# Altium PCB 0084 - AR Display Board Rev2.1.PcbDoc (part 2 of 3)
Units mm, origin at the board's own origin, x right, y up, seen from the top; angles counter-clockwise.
Board outline 127.7 x 27.2 mm, 4 copper layers (L1-TOP, L2-GND, L3-GND, L4-BOT), stack 1.571 mm thick; 141 components, 141 nets, 671 pads, 447 vias.
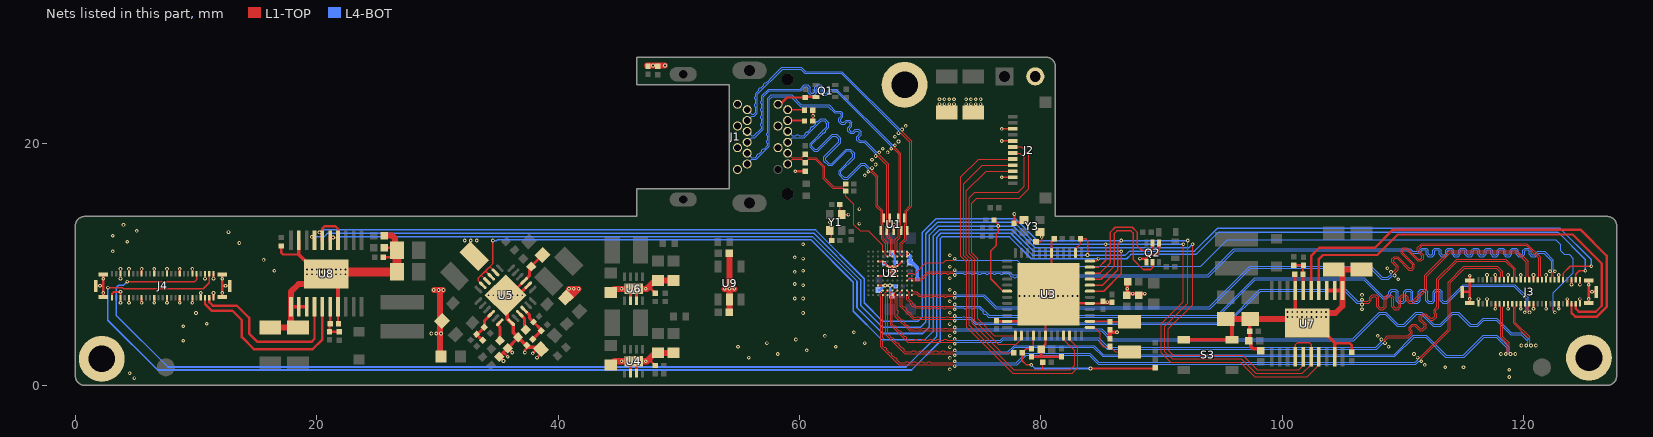
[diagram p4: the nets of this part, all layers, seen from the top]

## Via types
v1: diameter 0.3, hole 0.15, L1-TOP to L4-BOT, tented both sides, 445 vias
v2: diameter 0.25, hole 0.1, L1-TOP to L4-BOT, tented both sides, 2 vias

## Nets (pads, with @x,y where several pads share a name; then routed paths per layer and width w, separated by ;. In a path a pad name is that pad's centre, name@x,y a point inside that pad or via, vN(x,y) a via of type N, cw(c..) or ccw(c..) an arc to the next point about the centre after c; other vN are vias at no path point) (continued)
CN: C41.1 U5.18 | length 2
  L1-TOP w0.1: U5.18@34.944,4.999 U5.18@35.167,5.221
  L1-TOP w0.25: U5.18@35.167,5.221 35,5.055 35,5 35.182,4.818 C41.1@35.182,3.718
CP: C40.1 U5.21 | length 1.6
  L1-TOP w0.25: U5.21@36.829,5.929 37.2,5.557 37.2,4.547 C40.1@37.262,4.485
DP_AUX_CH_N: C3.2 J1.18 R2.2 U2.A4 | length 13.5
  L1-TOP w0.076: J1.18@59.015,18.34 59.389,18.714 60.186,18.714 R2.2@60.46,18.44 60.734,18.714 61.286,18.714 61.948,18.052 61.948,17.137 62.761,16.324 63.606,16.324 C3.2@63.83,16.1 63.83,15.67 64.5,15 64.5,13.326 65.026,12.8 65.7,12.8 66.9,11.6 U2.A4@66.9,11.075
DP_AUX_CH_P: C2.2 J1.16 R1.1 | length 6.8
  L1-TOP w0.076: J1.16@59.015,19.24 59.389,18.866 60.186,18.866 R1.1@60.46,19.14 60.734,18.866 61.349,18.866 62.1,18.116 62.1,17.2 62.824,16.476 63.606,16.476 C2.2@63.83,16.7
DP_CFG1: J1.4 R4.2 | length 1.4
  L1-TOP w0.15: J1.4@59.015,22.84 60.37,22.84 R4.2@60.41,22.8
DP_CFG2: J1.6 R3.2 | length 1.4
  L1-TOP w0.15: J1.6@59.015,21.94 60.37,21.94 R3.2@60.41,21.9
DP_HPD: J1.2 Q1.3 R23.2 | length 3.5
  L1-TOP w0.2: J1.2@58.215,23.09 58.975,23.85 R23.2@60.46,23.85 60.51,23.9 Q1.3@61.36,23.9
DP_LANE0_N: J1.10 U1.9 U2.A5 | length 28.7
  L1-TOP w0.076: v1(66,18) 66,17.808 66.5,17.308 66.5,14.876 66.905,14.471 66.905,13.395 66.945,13.355 66.945,12.171 67.3,11.816 U2.A5@67.3,11.075
  L4-BOT w0.076: J1.10@59.015,21.04 59.389,20.666 59.675,20.666 cw(c59.827,20.551) 59.98,20.666 60.2,20.666 60.341,20.666 60.45,20.775 cw(c60.639,20.802) 60.666,20.991 60.881,21.206 cw(c61.07,21.233) 61.097,21.422 61.312,21.637 cw(c61.501,21.664) 61.528,21.853 61.562,21.888 61.75,22.075 62.1,22.075 62.425,21.75 62.425,21.375 62.175,21.125 cw(c61.986,21.098) 61.959,20.909 61.875,20.825 61.025,19.975 61.025,19.8 61.275,19.55 61.459,19.55 62.709,20.8 63.066,20.8 63.402,20.463 63.402,20.102 62.175,18.875 62.175,18.65 62.448,18.377 62.662,18.377 63.862,19.577 64.213,19.577 64.577,19.213 64.577,18.877 63.425,17.725 63.425,17.5 63.7,17.225 63.934,17.225 65.112,18.402 65.405,18.402 65.808,18 v1(66,18)
DP_LANE0_P: J1.12 U1.1 U2.B5 | length 28.7
  L1-TOP w0.076: v1(65.7,17.7) 65.892,17.7 66.348,17.245 66.348,14.812 66.753,14.407 66.753,13.332 66.793,13.292 66.793,12.107 67.148,11.752 67.148,11.223 67.1,11.175 67.1,10.875 U2.B5@67.3,10.675
  L4-BOT w0.076: J1.12@59.015,20.14 59.389,20.514 60.404,20.514 61.813,21.923 62.037,21.923 62.273,21.687 62.273,21.438 60.873,20.038 60.873,19.737 61.212,19.398 61.523,19.398 62.773,20.648 63.002,20.648 63.25,20.4 63.25,20.166 62.023,18.938 62.023,18.587 62.384,18.225 62.725,18.225 63.925,19.425 64.15,19.425 64.425,19.15 64.425,18.941 63.273,17.788 63.273,17.437 63.637,17.073 63.998,17.073 65.175,18.25 65.342,18.25 65.7,17.892 v1(65.7,17.7)
DP_LANE1_N: J1.15 U1.8 U2.A6 | length 28.7
  L1-TOP w0.076: v1(66.6,19.3) 66.6,19.108 67.397,18.31 67.397,13.388 67.435,13.351 67.435,12.34 67.7,12.075 U2.A6@67.7,11.075
  L4-BOT w0.076: J1.15@55.665,19.24 56.039,18.866 56.351,18.866 56.458,18.974 56.458,19.082 56.566,19.189 56.674,19.189 56.889,19.405 56.889,19.513 56.997,19.621 57.105,19.621 57.321,19.836 57.36,19.876 57.36,20.028 57.284,20.104 57.284,20.257 57.36,20.333 57.36,20.638 57.284,20.714 57.284,20.866 57.36,20.942 57.36,21 57.36,23.776 57.659,24.075 59.341,24.075 60.163,23.252 62.455,23.252 62.98,22.728 63.394,22.728 63.59,22.532 63.59,22.243 63.402,22.055 63.402,21.892 63.508,21.785 63.671,21.785 63.859,21.974 64.149,21.974 64.344,21.778 64.344,21.489 64.156,21.3 64.156,21.137 64.262,21.031 64.425,21.031 64.614,21.219 64.903,21.219 65.099,21.024 65.099,20.734 64.91,20.546 64.91,20.383 65.017,20.277 65.431,20.277 65.707,20 66.408,19.3 v1(66.6,19.3)
DP_LANE1_P: J1.17 U1.2 U2.B6 | length 28.7
  L1-TOP w0.076: v1(66.3,19) 66.492,19 67.245,18.247 67.245,13.325 67.282,13.288 67.282,12.277 67.548,12.012 67.548,11.223 67.5,11.175 67.5,10.875 U2.B6@67.7,10.675
  L4-BOT w0.076: J1.17@55.665,18.34 56.039,18.714 56.414,18.714 57.512,19.812 57.512,23.712 57.723,23.923 59.277,23.923 60.1,23.1 62.392,23.1 62.917,22.575 63.331,22.575 63.438,22.469 63.438,22.306 63.249,22.118 63.249,21.828 63.445,21.633 63.734,21.633 63.922,21.821 64.086,21.821 64.192,21.715 64.192,21.552 64.004,21.363 64.004,21.074 64.199,20.879 64.489,20.879 64.677,21.067 64.84,21.067 64.946,20.961 64.946,20.797 64.758,20.609 64.758,20.32 64.953,20.124 65.368,20.124 65.555,19.937 66.3,19.192 v1(66.3,19)
DP_LANE2_N: J1.9 U1.4 U2.A7 | length 28.7
  L1-TOP w0.076: v1(67.9,19.9) 67.9,19.708 68.397,19.21 68.397,13.347 68.347,13.297 68.347,12.272 68.1,12.025 U2.A7@68.1,11.075
  L4-BOT w0.076: J1.9@55.665,21.04 56.039,20.666 56.226,20.666 56.86,21.301 56.86,21.453 56.784,21.529 56.784,21.682 56.86,21.758 56.86,22.063 56.784,22.139 56.784,22.291 56.86,22.367 56.86,22.672 56.784,22.748 56.784,22.901 56.86,22.977 56.86,23.282 56.784,23.358 56.784,23.51 56.86,23.587 56.86,23.775 56.86,23.976 57.434,24.55 59.85,24.55 60.053,24.55 60.395,24.893 60.672,24.893 60.876,24.688 60.876,24.323 60.992,24.207 61.142,24.207 61.257,24.323 61.257,24.688 61.462,24.893 61.738,24.893 61.943,24.688 61.943,24.323 62.058,24.207 62.209,24.207 62.551,24.55 63.058,24.55 67.708,19.9 v1(67.9,19.9)
DP_LANE2_P: J1.11 U1.7 U2.B7 | length 28.7
  L1-TOP w0.076: v1(67.6,19.6) 67.792,19.6 68.245,19.147 68.245,13.411 68.195,13.361 68.195,12.336 67.948,12.088 67.948,11.223 67.9,11.175 67.9,10.875 U2.B7@68.1,10.675
  L4-BOT w0.076: J1.11@55.665,20.14 56.039,20.514 56.289,20.514 57.012,21.237 57.012,23.912 57.498,24.398 59.918,24.398 60.116,24.398 60.458,24.74 60.609,24.74 60.724,24.625 60.724,24.26 60.929,24.055 61.205,24.055 61.41,24.26 61.41,24.625 61.525,24.74 61.675,24.74 61.791,24.625 61.791,24.26 61.995,24.055 62.272,24.055 62.614,24.398 62.995,24.398 67.6,19.792 v1(67.6,19.6)
DP_LANE3_N: J1.3 U1.5 U2.A8 | length 28.7
  L1-TOP w0.076: U2.A8@68.5,11.075 68.5,11.725 68.855,12.08 68.855,13.289 68.895,13.329 68.895,14.42 69.3,14.824 69.3,20.208 68.5,21.008 v1(68.5,21.2)
  L4-BOT w0.076: J1.3@55.665,22.84 56.039,22.466 56.2,22.466 56.36,22.626 56.36,22.9 56.36,23.052 56.284,23.129 56.284,23.281 56.36,23.357 56.36,23.662 56.284,23.738 56.284,23.891 56.36,23.967 56.36,24.1 56.36,24.176 56.5,24.316 56.615,24.43 56.615,24.538 56.722,24.646 56.83,24.646 57.046,24.861 57.046,24.969 57.153,25.077 57.261,25.077 57.477,25.292 57.584,25.4 58.537,26.352 60.148,26.352 60.5,26 63.508,26 68.308,21.2 v1(68.5,21.2)
DP_LANE3_P: J1.5 U1.6 U2.B8 | length 28.7
  L1-TOP w0.076: v1(68.2,20.9) 68.392,20.9 69.148,20.145 69.148,14.888 68.743,14.483 68.743,13.393 68.703,13.353 68.703,12.143 68.348,11.788 68.348,11.223 68.3,11.175 68.3,10.875 U2.B8@68.5,10.675
  L4-BOT w0.076: J1.5@55.665,21.94 56.039,22.314 56.263,22.314 56.512,22.563 56.512,24.112 58.6,26.2 60.084,26.2 60.437,25.848 63.445,25.848 68.2,21.092 v1(68.2,20.9)
FBL: C49.2 R35.2 R37.2 U7.16 | length 2.9
  L1-TOP w0.2: R35.2@100.96,9.95 C49.2@101.74,9.95 ; U7.16@101.75,7.844 U7.16@101.729,7.865 101.729,9.181 R37.2@101.71,9.2 101.71,9.92 C49.2@101.74,9.95 ; C49.2@101.76,9.97 C49.2@101.74,9.95
FBN: C36.2 R29.2 R30.2 U5.16 | length 3
  L1-TOP w0.25: R30.2@33.747,3.747 33.719,3.747 C36.2@33.233,4.233 33.316,4.233 R29.2@33.897,4.814 33.897,5.365 U5.16@34.46,5.929
FBP: C34.2 R26.2 R28.2 U5.22 | length 3.3
  L1-TOP w0.1: R26.2@38.597,4.519 R26.2@38.597,4.613
  L1-TOP w0.25: U5.22@37.182,6.282 37.644,5.82 37.644,5.566 C34.2@37.956,5.253 R26.2@38.597,4.613 ; R28.2@37.892,3.814 R26.2@38.597,4.519
FBR: C50.2 R36.2 R38.2 U8.16 | length 3
  L1-TOP w0.2: C50.2@20.96,4.43 20.96,4.45 C50.2@21.06,4.45 ; R38.2@21.01,5.1 21.118,5.208 U8.16@21.118,6.516 ; R38.2@21.06,5.1 C50.2@21.06,4.45 ; R36.2@21.86,4.45 C50.2@21.06,4.45
GND: C1.1 C4.1 C5.2 C6.2 C7.2 C8.2 C9.2 C10.1 C11.1 C12.1 C13.1 C14.1 C15.1 C16.1 C17.1 C18.1 C19.1 C20.1 C21.1 C22.1 C23.1 C24.1 C25.1 C26.2 C27.2 C28.1 C29.1 C30.1 C31.1 C32.1 C33.1 C35.2 C37.1 C38.1 C39.1 C40.2 C41.2 C42.1 C43.1 C44.1 C45.1 C46.1 C47.1 C48.1 C51.1 C52.1 C53.1 C54.1 C55.2 C56.2 C57.1 C58.2 C59.2 C60.1 C61.1 C62.1 CON2.2 J1.1 J1.7 J1.8 J1.13 J1.14 J1.19 J2.2 J2.8 J2.10 J3.1 J3.5 J3.6 J3.9 J3.10 J3.15 J3.16 J3.21 J3.22 J3.27 J3.28 J3.33 J3.34 J3.39 J3.40 J3.43 J3.46 J3.49 J3.50 J3.M J4.1 J4.5 J4.6 J4.9 J4.10 J4.15 J4.16 J4.21 J4.22 J4.27 J4.28 J4.33 J4.34 J4.39 J4.40 J4.43 J4.46 J4.49 J4.50 J4.M L4.2 pad.0 Q2.1 Q2.4 R2.1 R3.1 R4.1 R5.1 R27.1 R28.1 R34.1 R37.1 R38.1 R39.1 R40.1 R41.1 R42.1 S3.1 U1.3 U2.A9 U2.B9 U2.C3 U2.C4 U2.C8 U2.D5 U2.D6 U2.D7 U2.E5 U2.E6 U2.E7 U2.F3 U2.F4 U2.F5 U2.F6 U2.F7 U2.H3 U2.H4 U2.H5 U2.H6 U3.5 U3.18 U3.35 U3.42 U3.49 U4.2 U4.3 U4.9 U5.2 U5.3 U5.19 U5.25 U6.2 U6.3 U6.9 U7.9 U7.11 U7.12 U7.13 U7.17 U7.21 U8.9 U8.11 U8.12 U8.13 U8.17 U8.21 U9.2 Y1.2 Y1.4 Y3.2 Y3.4 | length 216.9
  L1-TOP w0.1: U5.25@35.775,7.467 U5.25@35.998,7.467 ; C40.2@36.626,3.848 36.815,3.848 C40.2@36.867,3.848 ; C33.1@38.71,10.796 C33.1@38.71,10.801 ; U4.9@46.01,1.75 v1(46.26,2) U4.9@46.51,1.75 ; U6.9@46.01,7.75 v1(46.26,8) U6.9@46.51,7.75 ; C43.1@48.01,8.35 C43.1@48.36,8.7 ; C32.1@48.11,2.35 48.46,2.7 C32.1@48.31,2.85 ; U3.49@78.375,5.3 80.375,7.3 U3.49@80.625,7.55 ; U3.49@80.875,7.8 U3.49@80.625,7.55 ; U3.49@81.375,6.8 U3.49@80.625,7.55 ; U7.21@101.23,5.979 101.709,5.5 U7.21@102.05,5.159 102.641,5.159 U7.21@102.741,5.159 ; U7.21@101.9,6 U7.21@103.25,4.65 ; U7.21@102.379,5.488 U7.21@102.841,5.95
  L1-TOP w0.125: v1(76.75,17.25) J2.2@77.66,17.25 77.635,17.25 J2.2@77.66,17.275 ; v1(76.75,20.25) J2.8@77.66,20.25 ; v1(76.75,21.25) J2.10@77.66,21.25
  L1-TOP w0.127: R3.1@61.11,21.9 R4.1@61.11,22.8 R4.1@61.135,22.775 ; Y1.2@62.46,12.85 62.63,12.68 C7.2@62.63,12 ; Y1.2@62.5,12.85 v1(62.5,13.5) ; Y1.4@63.29,14.32 Y1.4@63.46,14.15 ; C8.2@63.33,15 63.33,14.32 Y1.4@63.5,14.15 v1(64.05,14.15)
  L1-TOP w0.15: v1(77.8,14.2) 77.8,13.47 C59.2@77.76,13.43 77.83,13.5 78.41,13.5 Y3.4@78.61,13.7 ; C58.2@79.59,11.9 79.96,11.9 80.06,12 80.06,12.55 Y3.2@79.91,12.7
  L1-TOP w0.152: J4.1@3.05,7.25 3.05,7.6 3.2,7.75 v1(3.75,7.75) ; U2.H3@66.5,8.275 U2.H4@66.9,8.275 U2.H5@67.3,8.275 U2.H6@67.7,8.275 ; U2.F3@66.5,9.075 66.502,9.073 67.298,9.073 U2.F5@67.3,9.075 U2.F6@67.7,9.075 ; U2.C3@66.5,10.275 66.502,10.273 66.902,10.273 U2.D5@67.3,9.875 67.302,9.873 U2.D6@67.7,9.873 ; U2.E5@67.3,9.475 U2.E6@67.7,9.475 ; U2.F7@68.1,9.075 U2.F6@67.7,9.075 ; U2.E7@68.1,9.475 U2.E6@67.7,9.475 ; U2.C8@68.5,10.275 U2.D7@68.1,9.875 68.098,9.873 U2.D6@67.7,9.873 ; C13.1@76.3,5.355 C13.1@76.355,5.3 ; U2.F6@67.7,9.075 U2.E6@67.7,9.475 ; U2.E6@67.7,9.475 U2.D6@67.7,9.873 ; U2.B9@68.9,10.675 69,10.775 v1(69,10.875) 69,10.975 U2.A9@68.9,11.075 U2.B9@68.9,10.675
  L1-TOP w0.175: U3.5@84.05,6.8 C17.1@85.8,6.8
  L1-TOP w0.18: v1(3.75,6.85) J4.5@3.75,7.25 v1(3.75,7.75) ; v1(3.75,8.85) J4.6@3.75,9.25 v1(3.75,9.65) ; v1(4.45,6.85) J4.9@4.45,7.25 ; J4.10@4.45,9.25 v1(4.45,9.65) ; v1(5.5,6.85) J4.15@5.5,7.25 ; J4.16@5.5,9.25 v1(5.5,9.65) ; v1(6.55,6.85) J4.21@6.55,7.25 ; J4.22@6.55,9.25 v1(6.55,9.65) ; v1(7.6,6.85) J4.27@7.6,7.25 ; J4.28@7.6,9.25 v1(7.6,9.65) ; v1(8.65,6.85) J4.33@8.65,7.25 ; J4.34@8.65,9.25 v1(8.65,9.65) ; v1(9.7,6.85) J4.39@9.7,7.25 ; J4.40@9.7,9.25 v1(9.7,9.65) ; J4.43@10.4,7.25 v1(10.4,7.65) ; v1(10.75,8.85) J4.46@10.75,9.25 ; J4.49@11.45,7.25 v1(11.45,7.65) ; v1(11.45,8.85) J4.50@11.45,9.25 ; J3.M@115.385,6.815 J3.M@115.525,6.815 ; J3.M@115.385,8.685 J3.M@115.525,8.685 v1(115.525,9.085) ; J3.1@116.25,6.75 v1(116.25,7.15) ; J3.5@116.95,6.75 v1(116.95,7.15) ; J3.6@116.95,8.75 v1(116.95,9.15) ; v1(117.65,6.35) J3.9@117.65,6.75 ; J3.10@117.65,8.75 v1(117.65,9.15) ; v1(118.7,6.35) J3.15@118.7,6.75 ; J3.16@118.7,8.75 v1(118.7,9.15) ; v1(119.75,6.35) J3.21@119.75,6.75 ; J3.22@119.75,8.75 v1(119.75,9.15) ; v1(120.8,6.35) J3.27@120.8,6.75 ; J3.28@120.8,8.75 v1(120.8,9.15) ; v1(121.85,6.35) J3.33@121.85,6.75 ; J3.34@121.85,8.75 v1(121.85,9.15) ; v1(122.9,6.35) J3.39@122.9,6.75 ; J3.40@122.9,8.75 v1(122.9,9.15) ; J3.43@123.6,6.75 v1(123.6,7.15) ; v1(123.95,8.35) J3.46@123.95,8.75 ; J3.49@124.65,6.75 v1(124.65,7.15) ; v1(124.65,8.35) J3.50@124.65,8.75
  L1-TOP w0.2: J4.M@1.7,8.25 2.325,8.25 ; J4.M@2.325,7.315 v1(2.325,7.665) 2.325,8.25 ; J4.M@2.325,9.185 v1(2.325,8.835) 2.325,8.25 ; J4.M@12.175,7.315 12.175,8.25 ; J4.M@12.175,9.185 v1(12.175,8.835) 12.175,8.25 ; J4.M@12.8,8.25 12.175,8.25 ; R42.1@17.06,11.55 17.06,11 17.218,10.842 18.518,10.842 ; R38.1@21.71,5.1 21.768,5.158 U8.17@21.768,6.516 ; R41.1@25.51,10.6 C47.1@26.66,10.6 ; C56.2@25.61,11.4 26.66,11.4 C47.1@26.66,11.2 ; C35.2@35.118,2.382 v1(35.475,2.025) ; 35.456,2.719 35.481,2.719 v1(35.825,2.375) ; C41.2@35.818,3.082 36.175,2.725 v1(36.2,2.725) ; v1(37.25,2.725) 37.25,2.925 R28.1@37.5,3.175 ; v1(37.9,2.65) 38.225,2.975 C30.1@38.225,3.175 ; v1(38.25,2.3) 38.578,2.628 C30.1@38.578,3.001 ; v1@47.36,2 47.71,2 R27.1@48.06,1.65 ; v1@47.36,8 47.71,8 R34.1@48.06,7.65 ; v1(59.64,17.74) R2.1@60.46,17.74 ; U1.3@67.82,12.83 v1(67.82,13.34) ; C13.1@76.355,5.3 U3.49@78.375,5.3 ; C4.1@79.2,2.37 80,2.37 ; C9.2@80.01,3 80.01,2.38 80,2.37 ; C9.2@80.16,2.85 80.16,3.2 80.375,3.415 U3.49@80.375,7.3 ; U3.49@80.875,7.8 80.875,11.93 C12.1@81.095,12.15 ; U3.49@81.375,6.8 U3.5@84.05,6.8 ; C11.1@81.7,2.37 80,2.37 ; v1(88.2,10.5) 88.76,10.5 ; Q2.4@88.76,10.2 88.76,10.5 ; 89.76,11.4 89.76,11 89.56,10.8 88.9,10.8 88.76,10.66 88.76,10.5 ; R37.1@101.01,9.2 101.079,9.131 U7.17@101.079,7.865 ; U7.21@102.05,5.159 102.609,4.6 U7.21@103.2,4.6 ; 104.329,3.531 104.36,3.5 105.56,3.5 105.76,3.3 R40.1@105.76,2.75 ; J3.M@114.9,7.75 115.525,7.75 ; J3.M@115.525,6.815 v1(115.525,7.165) 115.525,7.75 ; J3.M@115.525,8.685 115.525,7.75 ; J3.M@125.375,6.815 v1(125.375,7.165) 125.375,7.75 ; J3.M@125.375,8.685 v1(125.375,8.335) 125.375,7.75 ; J3.M@126,7.75 125.375,7.75
  L1-TOP w0.25: C35.2@35.118,2.382 35.456,2.719 C41.2@35.818,3.082 36.682,3.945 C40.2@36.682,3.982 C40.2@36.815,3.848 ; U5.19@36.121,5.221 U5.19@36.325,5.018 ; R28.1@37.345,3.319 R28.1@37.397,3.319 ; U5.2@37.536,8.297 36.705,7.467 35.998,7.467 U5.3@37.182,8.651 37.644,9.113 37.644,9.73 C37.1@37.762,9.848 C33.1@38.71,10.796 ; U4.2@46.01,1.005 U4.9@46.01,1.75 ; U6.2@46.01,7.005 U6.9@46.01,7.75 ; U4.3@46.51,1.005 U4.9@46.51,1.75 ; U6.3@46.51,7.005 U6.9@46.51,7.75
  L1-TOP w0.3: U8.11@17.868,6.516 U8.12@18.518,6.516 U8.13@19.168,6.516 ; U8.9@18.518,12.016 18.518,10.842 19.625,9.735 U8.21@19.625,9.7 ; U8.21@19.925,8.35 U8.21@20.25,8.675 ; U8.21@20.468,8.893 U8.21@20.797,9.222 ; U8.21@21.322,8.697 U8.21@20.797,9.222 ; U8.21@21.372,8.647 U8.21@21.672,8.347 ; U8.17@21.768,6.516 U8.21@21.768,8.251 ; C38.1@30.326,5.332 C38.1@30.332,5.332 ; U5.25@35.775,7.467 35.775,5.525 36.3,5 36.3,4.364 C40.2@36.682,3.982 ; C40.2@36.815,3.848 R28.1@37.345,3.319 ; R28.1@37.397,3.319 R28.1@37.541,3.175 ; R28.1@37.5,3.175 C30.1@38.225,3.175 ; C15.1@85.135,6.87 C17.1@85.9,6.87 ; C26.2@85.725,3.88 C27.2@85.725,4.62 ; C27.2@85.8,4.4 v1(86.3,4.4) ; C16.1@87.1,7.45 C16.1@87.15,7.5 ; C10.1@87.21,8.6 87.15,8.6 C16.1@87.15,7.5 ; C14.1@88.1,7.4 C14.1@88.3,7.6 ; v1(88.6,7.6) C14.1@88.3,7.6 ; 89.76,11.4 Q2.1@89.76,11.8 ; S3.1@91.825,3.775 S3.1@95.825,3.775 95.825,4.975 C45.1@95.3,5.5 C45.1@94.925,5.125 ; C46.1@97.35,5.5 97.31,5.46 R39.1@97.31,4.5 97.31,3.8 C55.2@97.21,3.7 97.375,3.535 97.375,3.225 97.575,3.025 98.025,3.025 C57.1@98.2,2.85 ; U7.21@101.079,6.13 U7.17@101.079,7.865 ; U7.21@102.05,5.159 U7.21@102.379,5.488 ; U7.21@102.49,4.84 U7.21@102.96,4.84 ; U7.21@102.641,5.159 U7.21@102.96,4.84 ; U7.21@103.2,4.6 U7.21@102.96,4.84 ; U7.13@103.679,7.865 U7.12@104.329,7.865 U7.11@104.979,7.865 ; U7.9@104.329,2.365 104.329,3.531 103.02,4.84 U7.21@102.96,4.84 ; U8.21@19.625,9.7 20.103,9.222 U8.21@20.797,9.222 ; U8.21@19.625,9.7 20.319,9.7 U8.21@20.797,9.222 ; C16.1@87.15,7.5 87.25,7.6 v1(87.6,7.6) C14.1@88.3,7.6
  L1-TOP w0.5: C54.1@16.16,4.8 C53.1@17.868,4.8 ; C53.1@18.46,4.8 C53.1@17.868,4.8 ; U8.21@19.975,8.85 19.525,8.4 18.5,8.4 17.868,7.768 U8.11@17.868,6.516 C53.1@17.868,4.8 ; U8.21@20.797,9.222 U8.21@20.975,9.4 ; C60.1@25.61,12.4 26.25,12.4 26.5,12.15 26.5,11.56 C47.1@26.66,11.4 ; v1(29.7,7.9) v1(30.1,7.9) v1@30.451,7.9 ; v1@30.2,7.9 30.2,5.511 C38.1@30.378,5.332 30.2,5.154 30.2,2.5 C39.1@30.3,2.4 ; L4.2@33.068,10.69 L4.2@33.26,10.882 ; C29.1@40.9,7.531 C29.1@40.9,7.7 ; C28.1@44.36,1.7 44.66,2 v1(46.26,2) 47.36,2 48.06,2.7 C32.1@48.16,2.7 ; C42.1@44.36,7.7 44.66,8 v1(45.76,8) v1(46.26,8) v1(46.76,8) 47.36,8 48.06,8.7 C43.1@48.26,8.7 48.36,8.7 C44.1@49.56,8.7 ; C1.1@47.36,26.5 v1(48.86,26.5) ; C32.1@48.31,2.85 C32.1@48.16,2.7 ; C31.1@49.56,2.7 48.46,2.7 C32.1@48.26,2.7 C32.1@48.16,2.7 ; v1(53.8,8) v1(54.2,8) ; C5.2@54.175,6.05 54.2,6.075 U9.2@54.2,7.1 v1(54.2,8) ; C6.2@54.175,10.95 54.2,10.925 v1(54.2,8) ; v1(54.6,8) v1(54.2,8) ; C45.1@95.3,5.5 C46.1@97.35,5.5 101.709,5.5 U7.21@101.909,5.5 ; U7.21@101.9,6 104.4,6 104.979,6.579 U7.11@104.979,7.865 104.979,9.581 104.96,9.6 C52.1@104.26,9.6 C51.1@106.56,9.6 ; C29.1@40.634,7.266 40.966,7.266 v1(41.7,8) v1(41.3,8) v1@41.2,8 ; C29.1@40.634,7.266 40.634,7.434 C29.1@40.8,7.6 ; C29.1@40.634,7.266 40.8,7.431 C29.1@40.8,7.6 ; C29.1@40.8,7.6 C29.1@40.9,7.7 ; C29.1@40.9,7.7 v1(40.9,8) v1@41.2,8 ; C29.1@40.9,7.7 v1@41.2,8
  L1-TOP w0.75: U8.21@20.975,9.4 C48.1@26.66,9.4 26.66,10.6 C47.1@26.66,11.2
  L4-BOT w0.2: C18.1@66.56,7.9 66.66,7.9 67.035,8.275 v1(67.1,8.275) v1(67.5,8.275) ; C19.1@67.01,10.12 67.09,10.12 67.475,9.735 v1(67.475,9.68) ; C24.1@67.66,7.45 67.5,7.61 v1(67.5,8.275) ; C22.1@67.66,10.95 67.66,10.84 67.898,10.602 v1(67.898,9.68) ; C25.1@67.98,8.2 67.905,8.275 v1(67.5,8.275)
  L4-BOT w0.3: v1(69,10.875) 69.16,10.715 C20.1@69.16,10.2 69.31,10.2 69.74,9.77 C21.1@69.74,8.8
  other v1: 4.9,0.6 118.8,0.7 4.5,1 118.8,1.3 72.46,1.325 113.5,1.5 115,1.5 111.8,1.7 45.26,2 45.76,2 46.76,2 47.26,2 72.46,2.275 55.8,2.3 58.2,2.6 110.9,2.6 118.1,2.6 119.3,2.6 60.6,2.9 72.46,3.175 54.9,3.2 63,3.2 108.8,3.2 119.8,3.3 121,3.3 57.3,3.5 65.4,3.5 8.95,3.7 59.7,3.8 62.1,4.1 107.9,4.1 72.46,4.125 29.5,4.3 29.9,4.3 30.3,4.3 64.5,4.4 8.95,4.9 72.46,5.075 10.9,5.1 100.425,5.675 100.825,5.675 101.225,5.675 101.625,5.675 102.025,5.675 102.425,5.675 102.825,5.675 103.225,5.675 103.625,5.675 10,6 60.3,6 72.46,6.025 100.425,6.075 100.825,6.075 101.225,6.075 101.625,6.075 102.025,6.075 102.425,6.075 102.825,6.075 103.225,6.075 103.625,6.075 106.6,6.3 85.5,6.9 72.46,6.975 59.6,7.2 60.3,7.2 78.225,7.4 78.625,7.4 79.025,7.4 79.425,7.4 79.825,7.4 80.225,7.4 80.625,7.4 81.025,7.4 81.425,7.4 81.825,7.4 82.225,7.4 82.625,7.4 83.025,7.4 34.225,7.475 34.625,7.475 35.025,7.475 35.425,7.475 35.825,7.475 36.225,7.475 36.625,7.475 37.025,7.475 106.6,7.5 12.175,7.665 125.65,7.75 30.5,7.9 72.46,7.925 45.26,8 47.26,8 87.15,8 2.05,8.25 12.45,8.25 60.3,8.3 59.6,8.4 109.6,8.8 72.46,8.875 19.2,9.2 19.6,9.2 20,9.2 20.4,9.2 20.8,9.2 21.2,9.2 21.6,9.2 22,9.2 22.4,9.2 67.475,9.275 67.898,9.275 59.6,9.4 16.5,9.5 60.3,9.5 19.2,9.6 19.6,9.6 20,9.6 20.4,9.6 20.8,9.6 21.2,9.6 21.6,9.6 22,9.6 22.4,9.6 108.7,9.7 72.46,9.825 15.6,10.4 60.3,10.5 59.6,10.6 72.46,10.775 3.1,11.1 60.3,11.7 13.6,11.8 4.3,11.9 32.26,12 32.76,12 33.26,12 80.06,12.3 3.1,12.4 12.7,12.7 5.1,12.8 4,13.3 64.96,13.4 64.96,14.6 65.4,17.4 66.3,18.3 66,18.7 67.3,19.3 66.9,19.6 68.2,20.2 67.9,20.6 68.8,21.5 61.125,22.325 71.6,23.3 72,23.3 72.4,23.3 72.8,23.3 73.8,23.3 74.2,23.3 74.6,23.3 75,23.3 71.6,23.7 72,23.7 72.4,23.7 72.8,23.7 73.8,23.7 74.2,23.7 74.6,23.7 75,23.7 47.86,26.5
LCD_BIAS_EN: U3.7 U5.8 U5.9 U5.10 U5.11 | length 77.5
  L1-TOP w0.127: U5.11@33.753,8.297 33.4,8.65 33.4,8.9 33.6,9.1 ; U5.10@34.106,8.651 33.657,9.1 33.6,9.1 ; 34.371,9.8 U5.8@34.813,9.358 ; U5.9@34.46,9.004 34,9.464 34,9.5 ; v1(34.6,12) 34.6,10.1 34,9.5 ; U3.7@84.05,7.8 85.2,7.8 86.66,9.26 v1(86.66,11.1) ; 33.6,9.1 34,9.5
  L4-BOT w0.127: v1(34.6,12) 34.9,12 34.975,12.075 60.925,12.075 64.46,8.54 64.46,6.14 66.8,3.8 70.4,3.8 71.06,4.46 71.06,12.36 71.6,12.9 77.6,12.9 79.4,11.1 v1(86.66,11.1)
LCD_BL_EN: U3.8 U7.4 U7.6 U8.4 U8.6 | length 121.7
  L1-TOP w0.1: v1(92.16,12) 92.16,6.8 90.26,4.9 90.26,2.8 90.86,2.2 96.6,2.2 97.8,1 101.66,1 102.379,1.719 U7.6@102.379,2.365
  L1-TOP w0.127: U3.8@84.05,8.3 85.1,8.3 86.37,9.57 86.37,11.71 v1(86.66,12) ; U7.4@101.079,2.365 101.079,3.379 101.25,3.55 102.25,3.55 102.379,3.421 U7.6@102.379,2.365
  L1-TOP w0.2: U8.6@20.468,12.016 20.468,12.989 20.661,13.182 21.561,13.182 21.768,12.975 U8.4@21.768,12.016
  L1-TOP w0.3: v1(20.235,12.675) 20.468,12.675 U8.6@20.468,12.016
  L4-BOT w0.127: v1(20.235,12.675) 20.435,12.875 61.325,12.875 65.36,8.84 65.36,6.84 66.9,5.3 69.8,5.3 70.16,5.66 70.16,12.66 71.3,13.8 77.9,13.8 79.7,12 v1(92.16,12)
LCD_BL_FAULT: R10.1 U3.30 U7.5 U8.5 | length 114.7
  L1-TOP w0.1: v1(92.56,11.7) 92.56,6.7 90.56,4.7 90.56,2.9 90.96,2.5 96.7,2.5 97.9,1.3 101.36,1.3 101.729,1.669 U7.5@101.729,2.365
  L1-TOP w0.127: R10.1@76.11,13.7 76.46,13.35 76.46,12.7 76.31,12.55 76.31,11.61 75.835,11.135 75.835,8.825 76.86,7.8 U3.30@77.2,7.8
  L1-TOP w0.3: U8.5@21.118,12.016 21.118,12.25 v1(21.36,12.25)
  L4-BOT w0.127: v1(21.36,12.25) 21.65,12.25 21.725,12.325 61.075,12.325 64.76,8.64 64.76,6.44 66.9,4.3 70.2,4.3 70.76,4.86 70.76,12.46 71.5,13.2 v1(76.46,13.2) 77.7,13.2 79.5,11.4 92.26,11.4 v1(92.56,11.7)
LCD_BL_K1_L: J3.47 U7.14 | length 34.2
  L1-TOP w0.2: U7.14@103.029,7.865 103.029,10.469 103.36,10.8 107.86,10.8 109.56,12.5 124.05,12.5 126.46,10.09 126.46,6.6 125.96,6.1 124.56,6.1 124.3,6.36 J3.47@124.3,6.75
LCD_BL_K1_R: J4.47 U8.14 | length 14
  L1-TOP w0.2: J4.47@11.1,7.25 11.1,6.9 11.4,6.6 13.4,6.6 14.4,5.6 14.4,4.3 15.1,3.6 19.56,3.6 19.818,3.858 U8.14@19.818,6.516
LCD_BL_K2_L: J3.45 U7.15 | length 37.5
  L1-TOP w0.2: U7.15@102.379,7.865 102.379,10.719 103.06,11.4 107.66,11.4 109.16,12.9 124.7,12.9 126.86,10.74 126.86,6.5 126.06,5.7 124.26,5.7 123.95,6.01 J3.45@123.95,6.75
LCD_BL_K2_R: J4.45 U8.15 | length 15.6
  L1-TOP w0.2: J4.45@10.75,7.25 10.75,6.75 11.3,6.2 13,6.2 13.8,5.4 13.8,4 14.8,3 19.66,3 20.468,3.808 U8.15@20.468,6.516
LCD_BL_LEDPWM: J3.48 J4.48 U3.12 | length 151.4
  L1-TOP w0.127: v1(2.7,8.1) 3.9,8.1 4,8 10.6,8 11.1,8.5 J4.48@11.1,9.25 ; U3.12@84.05,10.3 84.56,10.3 v1(84.76,10.5) ; J3.48@124.3,8.75 124.3,9.2 124.6,9.5 v1(125.1,9.5)
  L4-BOT w0.127: v1(2.7,8.1) 2.7,5.4 6.825,1.275 69.275,1.275 71.66,3.66 71.66,12.16 71.8,12.3 77.4,12.3 79.2,10.5 v1(84.76,10.5) 87.1,10.5 87.45,10.85 92.85,10.85 94.7,12.7 122.825,12.7 125.1,10.425 v1(125.1,9.5)
LCD_BL_PWM: U3.11 U7.7 U8.7 | length 113.3
  L1-TOP w0.1: v1(91.8,11.7) 91.8,6.94 89.96,5.1 89.96,2.7 90.76,1.9 96.5,1.9 97.7,0.7 102.06,0.7 103.029,1.669 U7.7@103.029,2.365
  L1-TOP w0.127: U3.11@84.05,9.8 84.8,9.8 85.36,10.36 v1(85.36,11.7)
  L1-TOP w0.3: v1(19.585,12.3) U8.7@19.8,12.3
  L4-BOT w0.127: v1(19.585,12.3) 20.6,12.3 20.9,12.6 61.2,12.6 65.06,8.74 65.06,6.64 66.9,4.8 70,4.8 70.46,5.26 70.46,12.56 71.4,13.5 77.8,13.5 79.6,11.7 v1(85.36,11.7) 85.37,11.69 v1@91.8,11.69
LCD_RESET_N: J3.42 J4.42 R12.1 U3.14 | length 152.7
  L1-TOP w0.127: v1(4.3,8.6) 9.9,8.6 10.05,8.75 J4.42@10.05,9.25 ; U3.14@82.875,10.975 82.875,11.315 83.275,11.715 R12.1@83.275,12.15 83.71,12.15 83.86,12 v1(83.86,10.8) ; J3.42@123.25,8.75 123.25,9.275 123.85,9.875 v1(125.6,9.875)
  L4-BOT w0.127: v1(4.3,8.6) 4,8.3 3.6,8.3 3.4,8.1 3.4,5.8 7.675,1.525 68.825,1.525 71.36,4.06 71.36,12.26 71.7,12.6 77.5,12.6 79.3,10.8 v1(83.86,10.8) 87,10.8 87.325,11.125 92.725,11.125 94.6,13 123,13 125.6,10.4 v1(125.6,9.875)
MCU_EXT2: J2.7 U3.37 | length 23.1
  L1-TOP w0.1: J2.7@77.66,19.75 78.35,19.75 79,19.1 79,16.3 78.2,15.5 74.7,15.5 74.275,15.075 74.275,10.985 74.75,10.51 74.75,5.51 76.135,4.125 U3.37@77.875,4.125
MCU_EXT3: J2.6 U3.38 | length 24
  L1-TOP w0.1: J2.6@77.66,19.25 78.25,19.25 78.6,18.9 78.6,16.5 78.1,16 74.5,16 74.05,15.55 74.05,10.91 74.525,10.435 74.525,5.335 76.46,3.4 77.96,3.4 78.375,3.815 U3.38@78.375,4.125
MCU_LED0: Q2.2 U3.10 | length 10.2
  L1-TOP w0.127: U3.10@84.05,9.3 84.9,9.3 85.76,10.16 85.76,12.7 86.16,13.1 87.56,13.1 87.96,12.7 87.96,11.6 88.36,11.2 89.1,11.2 89.26,11.36 Q2.2@89.26,11.8
MCU_LED1: Q2.5 U3.9 | length 11.6
  L1-TOP w0.127: U3.9@84.05,8.8 85,8.8 86.06,9.86 86.06,12.56 86.3,12.8 87.46,12.8 87.66,12.6 87.66,10.4 88.46,9.6 89.1,9.6 89.26,9.76 Q2.5@89.26,10.2
MCU_RESET_N: C4.2 R13.2 R15.2 U3.40 | length 14.1
  L1-TOP w0.127: v1(79.2,1.7) 78.8,1.7 78.45,2.05 R13.2@78.45,2.7 78.78,3.03 C4.2@79.2,3.03 ; C4.2@79.26,3.03 C4.2@79.2,3.03 ; U3.40@79.375,4.125 79.375,3.215 79.19,3.03 C4.2@79.2,3.03 ; v1(84.1,1.4) 89.36,1.4 R15.2@89.46,1.5
  L4-BOT w0.127: v1(79.2,1.7) 79.5,1.4 v1(84.1,1.4)
MCU_SWD_CLK: J2.4 R9.1 U3.45 | length 30.5
  L1-TOP w0.1: J2.4@77.66,18.25 75.15,18.25 73.6,16.7 73.6,10.76 74.075,10.285 74.075,4.985 77.76,1.3 80.15,1.3 ; R9.1@80.15,1.9 80.15,1.3 ; U3.45@81.875,4.125 81.875,3.785 82.8,2.86 82.8,1.675 82.425,1.3 80.15,1.3
MCU_SWD_IO: J2.5 U3.46 | length 31.5
  L1-TOP w0.1: J2.5@77.66,18.75 74.85,18.75 73.375,17.275 73.375,10.685 73.85,10.21 73.85,4.81 77.66,1 82.6,1 83.05,1.45 83.05,3.11 82.375,3.785 U3.46@82.375,4.125
MCU_SWD_RESET_N: J2.3 R13.1 | length 20.1
  L1-TOP w0.1: J2.3@77.66,17.75 75.45,17.75 73.825,16.125 73.825,10.835 74.3,10.36 74.3,5.16 76.76,2.7 R13.1@77.75,2.7
MCU_XIN32: C26.1 U3.1 Y2.1 | length 4.6
  L1-TOP w0.1: U3.1@84.05,4.8 84.4,4.8 84.9,4.3 84.9,3.5 85.18,3.22 C26.1@85.725,3.22 86.17,2.775 Y2.1@87.325,2.775
MCU_XOUT32: C27.1 U3.2 Y2.0 | length 3.6
  L1-TOP w0.1: U3.2@84.05,5.3 U3.2@84.07,5.28 ; C27.1@85.705,5.3 C27.1@85.725,5.28 ; Y2.0@87.145,5.28 Y2.0@87.325,5.1
  L1-TOP w0.127: U3.2@84.05,5.3 C27.1@85.705,5.3 ; C27.1@85.725,5.28 Y2.0@87.145,5.28 ; Y2.0@87.325,5.1 Y2.0@87.325,5.275
MIPI_DSI00_0_N: J3.11 U2.J5 | length 63.9
  L1-TOP w0.076: U2.J5@67.3,7.875 67.1,7.675 67.1,7.392 67.144,7.348 67.144,4.2 68.721,2.624 72.736,2.624 v1(72.86,2.5) ; J3.11@118,6.75 118,6.575 118.099,6.476 118.099,3.986 118.624,3.461 118.624,2.724 v1(118.5,2.6)
  L4-BOT w0.076: v1(72.86,2.5) 72.984,2.624 77.324,2.624 77.848,3.148 84.352,3.148 85.1,2.4 109.316,2.4 110.916,4 111.859,4 113.512,2.348 115.063,2.348 116.716,4 117.7,4 118.624,3.076 118.624,2.724 v1(118.5,2.6)
MIPI_DSI00_0_P: J3.13 U2.K5 | length 63.9
  L1-TOP w0.076: U2.K5@67.3,7.475 67.3,4.26 67.36,4.2 67.383,4.177 67.598,3.962 67.706,3.962 67.814,3.854 67.814,3.746 68.029,3.531 68.137,3.531 68.245,3.423 68.245,3.315 68.461,3.1 68.568,3.1 68.676,2.992 68.676,2.884 68.784,2.776 68.995,2.776 69.3,2.776 69.376,2.852 69.528,2.852 69.604,2.776 69.909,2.776 69.985,2.852 70.138,2.852 70.214,2.776 70.519,2.776 70.595,2.852 70.747,2.852 70.824,2.776 71.128,2.776 71.205,2.852 71.357,2.852 71.433,2.776 71.738,2.776 71.814,2.852 71.967,2.852 72.043,2.776 72.348,2.776 72.5,2.776 72.736,2.776 v1(72.86,2.9) ; J3.13@118.35,6.75 118.35,6.575 118.251,6.476 118.251,4.049 118.776,3.524 118.776,2.724 v1(118.9,2.6)
  L4-BOT w0.076: v1(72.86,2.9) 72.984,2.776 77.261,2.776 77.784,3.3 84.416,3.3 85.163,2.552 109.252,2.552 110.852,4.152 111.923,4.152 113.575,2.5 115,2.5 116.652,4.152 117.763,4.152 118.776,3.139 118.776,2.724 v1(118.9,2.6)
MIPI_DSI00_1_N: J3.17 U2.J7 | length 63.9
  L1-TOP w0.076: U2.J7@68.1,7.875 67.9,7.675 67.9,7.392 67.948,7.345 67.948,5.697 69.121,4.524 72.736,4.524 v1(72.86,4.4) ; J3.17@119.05,6.75 119.05,6.575 119.149,6.476 119.149,5.136 120.324,3.961 120.324,3.424 v1(120.2,3.3)
  L4-BOT w0.076: v1(72.86,4.4) 72.984,4.524 84.976,4.524 85.8,3.7 105.9,3.7 108.1,5.9 108.509,5.9 109.509,4.9 110.125,4.9 111.125,5.9 111.484,5.9 112.484,4.9 113.125,4.9 114.125,5.9 114.534,5.9 115.534,4.9 116.2,4.9 116.692,5.392 117.708,5.392 118.9,4.2 119.8,4.2 120.324,3.676 120.324,3.424 v1(120.2,3.3)
MIPI_DSI00_1_P: J3.19 U2.K7 | length 63.9
  L1-TOP w0.076: U2.K7@68.1,7.475 68.1,6.4 68.1,6.217 68.176,6.141 68.176,5.989 68.1,5.912 68.1,5.76 68.214,5.646 68.429,5.431 68.537,5.431 68.645,5.323 68.645,5.215 68.86,5 68.968,5 69.076,4.892 69.076,4.784 69.184,4.676 69.231,4.676 69.536,4.676 69.612,4.752 69.764,4.752 69.841,4.676 70.145,4.676 70.222,4.752 70.374,4.752 70.45,4.676 70.755,4.676 70.831,4.752 70.984,4.752 71.06,4.676 71.365,4.676 71.441,4.752 71.593,4.752 71.669,4.676 71.974,4.676 72.05,4.752 72.203,4.752 72.279,4.676 72.584,4.676 72.736,4.676 v1(72.86,4.8) ; J3.19@119.4,6.75 119.4,6.575 119.301,6.476 119.301,5.199 120.476,4.024 120.476,3.424 v1(120.6,3.3)
  L4-BOT w0.076: v1(72.86,4.8) 72.984,4.676 85.039,4.676 85.863,3.852 105.837,3.852 108.037,6.052 108.573,6.052 109.573,5.052 110.062,5.052 111.062,6.052 111.548,6.052 112.548,5.052 113.062,5.052 114.062,6.052 114.598,6.052 115.598,5.052 116.137,5.052 116.629,5.545 117.771,5.545 118.963,4.352 119.863,4.352 120.476,3.739 120.476,3.424 v1(120.6,3.3)
MIPI_DSI00_2_N: J3.24 U2.J8 | length 63.9
  L1-TOP w0.076: U2.J8@68.5,7.875 68.3,7.675 68.3,7.392 68.348,7.345 68.348,6.552 69.426,5.474 72.736,5.474 v1(72.86,5.35) ; v1(106.6,6.7) 106.724,6.824 107.153,6.824 107.381,7.051 107.381,7.223 107.519,7.361 107.7,7.361 107.838,7.223 107.838,6.514 108.066,6.286 108.373,6.286 108.6,6.514 108.6,7.223 108.738,7.361 108.919,7.361 109.057,7.223 109.057,6.514 109.285,6.286 109.592,6.286 109.819,6.514 109.819,7.223 109.958,7.361 110.138,7.361 110.277,7.223 110.277,7.051 110.504,6.824 110.839,6.824 111.952,7.937 111.952,9.052 113.9,11 119.4,11 120.199,10.201 120.199,9.024 120.1,8.925 J3.24@120.1,8.75
  L4-BOT w0.076: v1(72.86,5.35) 72.984,5.474 74.126,5.474 74.552,5.048 95.448,5.048 98.2,7.8 105.184,7.8 106.161,6.824 106.476,6.824 v1(106.6,6.7)
MIPI_DSI00_2_P: J3.26 U2.K8 | length 63.9
  L1-TOP w0.076: U2.K8@68.5,7.475 68.5,6.616 68.608,6.508 68.716,6.508 68.823,6.4 68.823,6.292 69.039,6.077 69.147,6.077 69.254,5.969 69.254,5.861 69.47,5.646 69.489,5.626 69.642,5.626 69.718,5.702 69.87,5.702 69.946,5.626 70.251,5.626 70.327,5.702 70.48,5.702 70.556,5.626 70.861,5.626 70.937,5.702 71.089,5.702 71.166,5.626 71.47,5.626 71.547,5.702 71.699,5.702 71.775,5.626 72.08,5.626 72.156,5.702 72.309,5.702 72.385,5.626 72.69,5.626 72.736,5.626 v1(72.86,5.75) ; v1(106.6,7.1) 106.724,6.976 107.09,6.976 107.229,7.114 107.229,7.286 107.456,7.514 107.763,7.514 107.991,7.286 107.991,6.577 108.129,6.439 108.31,6.439 108.448,6.577 108.448,7.286 108.675,7.514 108.982,7.514 109.21,7.286 109.21,6.577 109.348,6.439 109.529,6.439 109.667,6.577 109.667,7.286 109.895,7.514 110.201,7.514 110.429,7.286 110.429,7.114 110.567,6.976 110.776,6.976 111.8,8 111.8,9.116 113.837,11.152 119.463,11.152 120.351,10.264 120.351,9.024 120.45,8.925 J3.26@120.45,8.75
  L4-BOT w0.076: v1(72.86,5.75) 72.984,5.626 73.3,5.626 73.452,5.626 73.529,5.702 73.681,5.702 73.757,5.626 73.8,5.626 74.189,5.626 74.616,5.2 95.384,5.2 98.137,7.952 105.248,7.952 106.224,6.976 106.476,6.976 v1(106.6,7.1)
MIPI_DSI00_3_N: J3.12 U2.J4 | length 63.9
  L1-TOP w0.076: U2.J4@66.9,7.875 66.7,7.675 66.7,7.343 66.744,7.299 66.744,3.2 68.221,1.724 72.736,1.724 v1(72.86,1.6) ; v1(111.5,2) 111.5,2.192 113.9,4.592 113.9,8.5 115.1,9.7 117.737,9.7 118.099,9.338 118.099,9.024 118,8.925 J3.12@118,8.75
  L4-BOT w0.076: v1(72.86,1.6) 72.984,1.724 78.024,1.724 78.8,2.5 84,2.5 84.745,1.755 111.063,1.755 111.308,2 v1(111.5,2)
MIPI_DSI00_3_P: J3.14 U2.K4 | length 63.9
  L1-TOP w0.076: U2.K4@66.9,7.475 66.9,4.1 66.9,3.948 66.976,3.871 66.976,3.719 66.9,3.643 66.9,3.338 66.9,3.26 67.008,3.152 67.116,3.152 67.223,3.044 67.223,2.937 67.439,2.721 67.547,2.721 67.654,2.613 67.654,2.506 67.87,2.29 67.978,2.29 68.085,2.182 68.085,2.075 68.284,1.876 68.436,1.876 68.741,1.876 68.817,1.952 68.97,1.952 69.046,1.876 69.351,1.876 69.427,1.952 69.579,1.952 69.655,1.876 69.96,1.876 70.036,1.952 70.189,1.952 70.265,1.876 70.57,1.876 70.646,1.952 70.798,1.952 70.875,1.876 71,1.876 72.736,1.876 v1(72.86,2) ; v1(111.2,2.3) 111.392,2.3 113.748,4.655 113.748,8.563 115.037,9.852 117.8,9.852 118.251,9.401 118.251,9.024 118.35,8.925 J3.14@118.35,8.75
  L4-BOT w0.076: v1(72.86,2) 72.984,1.876 77.961,1.876 78.737,2.652 84.063,2.652 84.808,1.908 111,1.908 111.2,2.108 v1(111.2,2.3)
MIPI_DSI00_C_N: J3.18 U2.J6 | length 63.9
  L1-TOP w0.076: U2.J6@67.7,7.875 67.5,7.675 67.5,7.392 67.548,7.345 67.548,4.997 68.971,3.574 72.736,3.574 v1(72.86,3.45) ; v1(108.5,3.5) 108.5,3.692 108.755,3.948 110.448,3.948 110.738,4.238 110.738,4.516 110.646,4.608 110.646,4.76 110.817,4.931 110.97,4.931 111.368,4.533 111.647,4.533 111.907,4.793 111.907,5.071 111.508,5.47 111.508,5.623 111.679,5.793 111.832,5.793 112.23,5.395 112.509,5.395 112.769,5.655 112.769,5.934 112.678,6.025 112.678,6.178 112.952,6.452 112.952,8.752 114.5,10.3 118.46,10.3 119.149,9.611 119.149,9.024 119.05,8.925 J3.18@119.05,8.75
  L4-BOT w0.076: v1(72.86,3.45) 72.984,3.574 76.674,3.574 76.892,3.792 84.708,3.792 85.5,3 107.808,3 108.308,3.5 v1(108.5,3.5)
MIPI_DSI00_C_P: J3.20 U2.K6 | length 63.9
  L1-TOP w0.076: U2.K6@67.7,7.475 67.7,5.3 67.7,5.148 67.7,5.06 67.808,4.952 67.916,4.952 68.023,4.844 68.023,4.737 68.239,4.521 68.347,4.521 68.454,4.413 68.454,4.306 68.67,4.09 68.778,4.09 68.885,3.982 68.885,3.875 69.034,3.726 69.186,3.726 69.491,3.726 69.567,3.802 69.72,3.802 69.796,3.726 70.101,3.726 70.177,3.802 70.329,3.802 70.405,3.726 70.71,3.726 70.786,3.802 70.939,3.802 71.015,3.726 71.32,3.726 71.396,3.802 71.548,3.802 71.625,3.726 71.929,3.726 72.006,3.802 72.158,3.802 72.234,3.726 72.3,3.726 72.736,3.726 v1(72.86,3.85) ; v1(108.2,3.8) 108.392,3.8 108.692,4.1 110.384,4.1 110.585,4.301 110.585,4.453 110.494,4.545 110.494,4.824 110.754,5.084 111.033,5.084 111.431,4.685 111.584,4.685 111.755,4.856 111.755,5.008 111.356,5.407 111.356,5.686 111.616,5.946 111.895,5.946 112.293,5.547 112.446,5.547 112.617,5.718 112.617,5.87 112.525,5.962 112.525,6.241 112.8,6.516 112.8,8.816 114.437,10.452 118.523,10.452 119.301,9.674 119.301,9.024 119.4,8.925 J3.20@119.4,8.75
  L4-BOT w0.076: v1(72.86,3.85) 72.984,3.726 76.611,3.726 76.829,3.945 84.771,3.945 85.563,3.152 107.745,3.152 108.2,3.608 v1(108.2,3.8)
MIPI_DSI01_0_N: J3.38 U2.G9 | length 63.9
  L1-TOP w0.076: U2.G9@68.9,8.675 69.1,8.875 69.383,8.875 69.43,8.827 70.027,8.827 70.626,9.426 72.736,9.426 v1(72.86,9.55) ; J3.38@122.55,8.75 122.55,8.925 122.451,9.024 122.451,9.326 v1(122.575,9.45) v1@122.563,9.45
  L4-BOT w0.076: v1(72.86,9.55) 72.984,9.426 77.334,9.426 77.608,9.152 93.837,9.152 95.984,11.3 110.6,11.3 110.8,11.1 111.297,11.1 111.568,11.371 111.898,11.371 112.076,11.193 112.076,10.918 112.165,10.829 112.369,10.829 112.457,10.918 112.457,11.193 112.635,11.371 112.965,11.371 113.143,11.193 113.143,10.918 113.232,10.829 113.435,10.829 113.524,10.918 113.524,11.193 113.702,11.371 114.032,11.371 114.21,11.193 114.21,10.918 114.299,10.829 114.502,10.829 114.591,10.918 114.591,11.193 114.769,11.371 115.099,11.371 115.277,11.193 115.277,10.918 115.365,10.829 115.569,10.829 115.658,10.918 115.658,11.193 115.836,11.371 116.166,11.371 116.344,11.193 116.344,10.918 116.432,10.829 116.636,10.829 116.725,10.918 116.725,11.193 116.902,11.371 117.232,11.371 117.41,11.193 117.41,10.918 117.499,10.829 117.703,10.829 117.791,10.918 117.791,11.193 117.969,11.371 118.299,11.371 118.477,11.193 118.477,10.918 118.566,10.829 118.769,10.829 118.858,10.918 118.858,11.193 119.036,11.371 119.366,11.371 119.544,11.193 119.544,10.918 119.633,10.829 119.836,10.829 119.925,10.918 119.925,11.193 120.103,11.371 120.433,11.371 120.611,11.193 120.611,10.918 120.699,10.829 120.903,10.829 121.174,11.1 121.716,11.1 122.451,10.364 122.451,9.574 v1(122.575,9.45)
MIPI_DSI01_0_P: J3.36 U2.G10 | length 64
  L1-TOP w0.076: U2.G10@69.3,8.675 70.091,8.675 70.689,9.274 70.7,9.274 70.924,9.274 71,9.198 71.152,9.198 71.228,9.274 71.533,9.274 71.609,9.198 71.762,9.198 71.838,9.274 72.143,9.274 72.219,9.198 72.371,9.198 72.448,9.274 72.6,9.274 72.736,9.274 v1(72.86,9.15) ; v1@122.187,9.45 v1(122.175,9.45) 122.299,9.326 122.299,9.024 122.2,8.925 J3.36@122.2,8.75
  L4-BOT w0.076: v1(72.86,9.15) 72.984,9.274 73.1,9.274 73.252,9.274 73.557,9.274 73.633,9.198 73.786,9.198 73.862,9.274 74.167,9.274 74.243,9.198 74.395,9.198 74.472,9.274 74.776,9.274 74.853,9.198 75.005,9.198 75.081,9.274 75.386,9.274 75.462,9.198 75.615,9.198 75.691,9.274 75.996,9.274 76.072,9.198 76.224,9.198 76.3,9.274 76.605,9.274 76.681,9.198 76.834,9.198 76.91,9.274 77.215,9.274 77.271,9.274 77.544,9 77.697,9 77.773,8.924 77.925,8.924 78.002,9 78.306,9 78.383,8.924 78.535,8.924 78.611,9 78.916,9 78.992,8.924 79.145,8.924 79.221,9 93.9,9 96.048,11.148 110.537,11.148 110.737,10.948 111.361,10.948 111.632,11.219 111.835,11.219 111.924,11.13 111.924,10.855 112.102,10.677 112.432,10.677 112.61,10.855 112.61,11.13 112.698,11.219 112.902,11.219 112.991,11.13 112.991,10.855 113.169,10.677 113.499,10.677 113.677,10.855 113.677,11.13 113.765,11.219 113.969,11.219 114.058,11.13 114.058,10.855 114.235,10.677 114.565,10.677 114.743,10.855 114.743,11.13 114.832,11.219 115.036,11.219 115.124,11.13 115.124,10.855 115.302,10.677 115.632,10.677 115.81,10.855 115.81,11.13 115.899,11.219 116.102,11.219 116.191,11.13 116.191,10.855 116.369,10.677 116.699,10.677 116.877,10.855 116.877,11.13 116.966,11.219 117.169,11.219 117.258,11.13 117.258,10.855 117.436,10.677 117.766,10.677 117.944,10.855 117.944,11.13 118.032,11.219 118.236,11.219 118.325,11.13 118.325,10.855 118.503,10.677 118.833,10.677 119.011,10.855 119.011,11.13 119.099,11.219 119.303,11.219 119.392,11.13 119.392,10.855 119.569,10.677 119.899,10.677 120.077,10.855 120.077,11.13 120.166,11.219 120.37,11.219 120.458,11.13 120.458,10.855 120.636,10.677 120.966,10.677 121.237,10.948 121.652,10.948 122.299,10.301 122.299,9.574 v1(122.175,9.45)
MIPI_DSI01_1_N: J3.32 U2.J10 | length 63.9
  L1-TOP w0.076: U2.J10@69.3,7.875 69.424,7.751 69.724,7.751 69.949,7.526 72.736,7.526 v1(72.86,7.65) ; v1(109,9.4) 109.192,9.4 109.445,9.653 109.445,9.816 109.079,10.182 109.079,10.472 109.275,10.667 109.564,10.667 110.522,9.709 110.686,9.709 110.792,9.815 110.792,9.978 109.834,10.936 109.834,11.226 110.029,11.421 110.319,11.421 111.277,10.463 111.44,10.463 111.546,10.57 111.546,10.733 111.18,11.099 111.18,11.388 111.545,11.752 120.263,11.752 121.401,10.614 121.401,9.024 121.5,8.925 J3.32@121.5,8.75
  L4-BOT w0.076: v1(72.86,7.65) 72.984,7.526 75.289,7.526 76.316,6.5 93.96,6.5 97.312,9.852 107.363,9.852 108.263,8.952 108.745,8.952 109,9.208 v1(109,9.4)
MIPI_DSI01_1_P: J3.30 U2.K10 | length 63.9
  L1-TOP w0.076: U2.K10@69.3,7.475 69.424,7.599 69.661,7.599 69.886,7.374 69.9,7.374 70.114,7.374 70.19,7.298 70.343,7.298 70.419,7.374 70.724,7.374 70.8,7.298 70.952,7.298 71.028,7.374 71.333,7.374 71.409,7.298 71.562,7.298 71.638,7.374 71.943,7.374 72.019,7.298 72.171,7.298 72.248,7.374 72.4,7.374 72.736,7.374 v1(72.86,7.25) ; v1(109.3,9.1) 109.3,9.292 109.598,9.59 109.598,9.879 109.232,10.245 109.232,10.408 109.338,10.515 109.501,10.515 110.459,9.557 110.749,9.557 110.944,9.752 110.944,10.042 109.986,11 109.986,11.163 110.092,11.269 110.256,11.269 111.214,10.311 111.503,10.311 111.699,10.507 111.699,10.796 111.333,11.162 111.333,11.325 111.608,11.6 120.2,11.6 121.249,10.551 121.249,9.024 121.15,8.925 J3.30@121.15,8.75
  L4-BOT w0.076: v1(72.86,7.25) 72.984,7.374 75.226,7.374 76.252,6.348 94.023,6.348 97.376,9.7 107.3,9.7 108.2,8.8 108.808,8.8 109.108,9.1 v1(109.3,9.1)
MIPI_DSI01_2_N: J3.25 U2.J9 | length 63.9
  L1-TOP w0.076: U2.J9@68.9,7.875 69.1,7.675 69.1,7.375 69.05,7.325 69.05,7.166 69.639,6.576 72.736,6.576 v1(72.86,6.7) ; J3.25@120.45,6.75 120.45,6.575 120.351,6.476 120.351,6.174 v1(120.475,6.05) v1@120.463,6.05
  L4-BOT w0.076: v1(72.86,6.7) 72.984,6.576 74.939,6.576 75.716,5.8 94.6,5.8 97.7,8.9 106.8,8.9 108.375,7.325 108.6,7.325 108.829,7.554 108.829,7.755 109.026,7.953 109.394,7.953 109.591,7.755 109.591,7.06 109.698,6.952 109.94,6.952 110.048,7.06 110.048,7.755 110.245,7.953 110.613,7.953 110.81,7.755 110.81,7.06 110.918,6.952 111.159,6.952 111.267,7.06 111.267,7.755 111.464,7.953 111.832,7.953 112.029,7.755 112.029,7.06 112.137,6.952 112.378,6.952 112.486,7.06 112.486,7.755 112.683,7.953 113.051,7.953 113.248,7.755 113.248,7.06 113.356,6.952 113.598,6.952 114.998,8.352 119.248,8.352 120.351,7.249 120.351,6.174 v1(120.475,6.05)
MIPI_DSI01_2_P: J3.23 U2.K9 | length 63.9
  L1-TOP w0.076: U2.K9@68.9,7.475 68.898,7.473 68.898,7.102 69.005,6.995 69.221,6.779 69.221,6.671 69.329,6.564 69.436,6.564 69.576,6.424 69.729,6.424 70.033,6.424 70.11,6.348 70.262,6.348 70.338,6.424 70.643,6.424 70.719,6.348 70.872,6.348 70.948,6.424 71.253,6.424 71.329,6.348 71.481,6.348 71.557,6.424 71.862,6.424 71.938,6.348 72.091,6.348 72.167,6.424 72.3,6.424 72.736,6.424 v1(72.86,6.3) ; v1@120.087,6.05 v1(120.075,6.05) 120.199,6.174 120.199,6.476 120.1,6.575 J3.23@120.1,6.75
  L4-BOT w0.076: v1(72.86,6.3) 72.984,6.424 73.1,6.424 73.252,6.424 73.557,6.424 73.633,6.348 73.786,6.348 73.862,6.424 74.167,6.424 74.243,6.348 74.395,6.348 74.472,6.424 74.7,6.424 74.876,6.424 74.984,6.316 75.199,6.101 75.199,5.993 75.307,5.885 75.415,5.885 75.652,5.648 94.663,5.648 97.763,8.748 106.737,8.748 108.312,7.173 108.663,7.173 108.981,7.49 108.981,7.692 109.089,7.8 109.33,7.8 109.438,7.692 109.438,6.997 109.635,6.8 110.003,6.8 110.2,6.997 110.2,7.692 110.308,7.8 110.55,7.8 110.657,7.692 110.657,6.997 110.854,6.8 111.222,6.8 111.419,6.997 111.419,7.692 111.527,7.8 111.769,7.8 111.877,7.692 111.877,6.997 112.074,6.8 112.442,6.8 112.639,6.997 112.639,7.692 112.746,7.8 112.988,7.8 113.096,7.692 113.096,6.997 113.293,6.8 113.661,6.8 115.061,8.2 119.184,8.2 120.199,7.186 120.199,6.174 v1(120.075,6.05)
MIPI_DSI01_3_N: J3.37 U2.F9 | length 63.9
  L1-TOP w0.076: U2.F9@68.9,9.075 69.1,9.275 69.383,9.275 69.43,9.227 69.527,9.227 70.452,10.152 71.897,10.152 72.121,10.376 72.736,10.376 v1(72.86,10.5) ; J3.37@122.55,6.75 122.55,6.575 122.451,6.476 122.451,6.174 v1(122.575,6.05) v1@122.563,6.05
  L4-BOT w0.076: v1(72.86,10.5) 72.984,10.376 78.024,10.376 78.548,9.852 93.237,9.852 95.437,12.052 122.663,12.052 123.052,11.663 123.052,11.148 123.348,10.852 123.748,10.852 124.1,10.5 124.1,9.313 122.451,7.664 122.451,6.174 v1(122.575,6.05)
